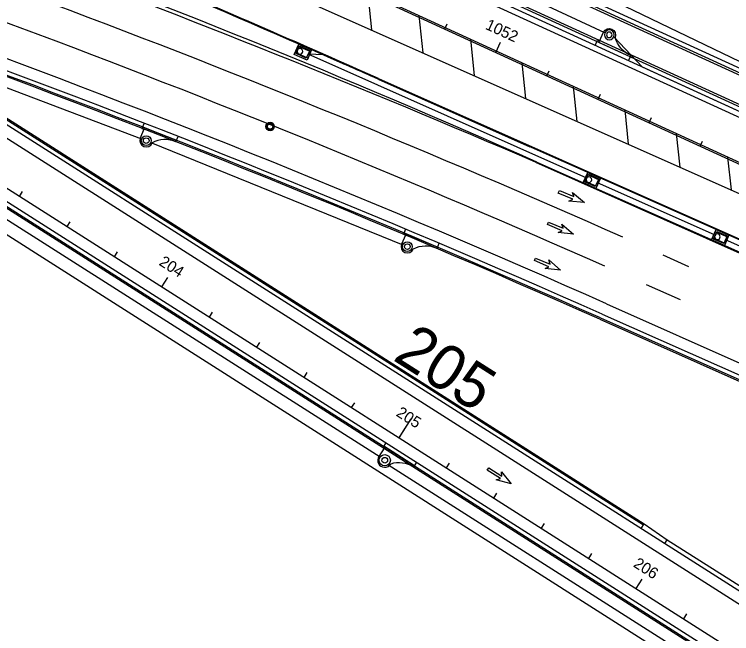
# Model space of a CAD drawing. Extents: x 468143 to 491361, y 1438528 to 1468730.
# Drawn here: x 487342.4 to 487597.7, y 1467031.9 to 1467252.2 of the extents above; entities that cross this region are included whole.
import ezdxf

# ---------------------------------------------------------------- set-up
doc = ezdxf.new("R2010")
doc.units = 0
doc.layers.add('Default', color=7, linetype='Continuous')
doc.layers.add('Xreference_dp', color=7, linetype='Continuous')

# ---------------------------------------------------------------- blocks, each defined once
blk = doc.blocks.new('POINT_DISPLAY')
at = {"layer": 'Default'}
blk.add_line((0, 0), (0, 0), dxfattribs=at)
blk = doc.blocks.new('InltCurb1_35')
at = {"layer": 'Default'}
for p, q in [((2.25, 2), (2.25, 5.5)), ((-10, 2), (-10, 0)), ((-10, 1.5), (3, 1.5)), ((3, 2), (2.25, 2)), ((3, 0), (3, 2))]:
    blk.add_line(p, q, dxfattribs=at)
for radius in [1.75, 1]:
    blk.add_circle((0, 5.5), radius, dxfattribs=at)
for centre, radius, start, end in [((0, 5.5), 2.25, 0, 180), ((-9.85, 12), 10, 269.1432, 319.4677)]:
    blk.add_arc(centre, radius, start, end, dxfattribs=at)
for p in [(0, 7.75), (-1.75, 5.5), (-1.75, 5.5), (-1.6, 6.2), (-1.22, 6.76), (-0.66, 7.12), (0, 7.25), (0, 7.25), (0, 5.5), (0, 5.5), (0.7, 7.1), (1.26, 6.72), (1.62, 6.16), (1.75, 5.5), (1.75, 5.5), (-1.62, 4.84), (-1.26, 4.28), (-0.7, 3.9), (0, 3.75), (0, 3.75), (0.66, 3.88), (1.22, 4.24), (1.6, 4.8), (0, 0), (0, 0)]:
    blk.add_blockref('POINT_DISPLAY', p, dxfattribs=at)
blk = doc.blocks.new('InltCurb7_40')
at = {"layer": 'Default'}
for p, q in [((2.5, 4), (-2.5, 4)), ((-2.5, 4), (-2.5, 0)), ((2.5, 3.25), (-2.5, 3.25)), ((2.5, 0), (2.5, 4)), ((-2.5, 0.75), (2.5, 0.75)), ((-2.5, 0), (2.5, 0))]:
    blk.add_line(p, q, dxfattribs=at)
blk.add_lwpolyline([(-2, 0.5), (2, 0.5), (2, 3.5), (-2, 3.5)], close=True, dxfattribs=at)
blk.add_circle((-1.04, 2.19), 1, dxfattribs=at)
for p in [(-2, 3.5), (0, 4), (0, 3.5), (0, 3.5), (2, 3.5), (-2, 2), (-2, 2), (-2, 0.5), (0, 2), (0, 2), (0, 0.5), (0, 0.5), (0, 0), (0, 0), (2, 2), (2, 2), (2, 0.5)]:
    blk.add_blockref('POINT_DISPLAY', p, dxfattribs=at)
blk = doc.blocks.new('MH2')
at = {"layer": 'Default'}
for p, q in [((-1.25, 0.03), (-1.05, 0.03)), ((-0.9, 0.87), (-0.76, 0.73)), ((-0.87, 0.9), (-0.73, 0.76)), ((-0.03, 1.25), (-0.03, 1.05)), ((0.03, 1.25), (0.03, 1.05)), ((0.87, 0.9), (0.73, 0.76)), ((0.9, 0.87), (0.76, 0.73)), ((1.05, 0.03), (1.25, 0.03)), ((-1.25, -0.03), (-1.05, -0.03)), ((-0.76, -0.73), (-0.9, -0.87)), ((-0.73, -0.76), (-0.87, -0.9)), ((-0.03, -1.05), (-0.03, -1.25)), ((0.03, -1.05), (0.03, -1.25)), ((0.73, -0.76), (0.87, -0.9)), ((0.76, -0.73), (0.9, -0.87)), ((1.05, -0.03), (1.25, -0.03))]:
    blk.add_line(p, q, dxfattribs=at)
for radius in [1.5, 1.25, 1.05, 1, 0.958]:
    blk.add_circle((0, 0), radius, dxfattribs=at)
for p in [(-1, 0), (-0.71, 0.71), (0, 1.5), (0, 1), (0, 0), (0, 0), (0, 0), (0.71, 0.71), (1, 0), (-0.71, -0.71), (0, -1), (0, -1.5), (0.71, -0.71)]:
    blk.add_blockref('POINT_DISPLAY', p, dxfattribs=at)
blk = doc.blocks.new('DAMerge_2')
at = {"layer": 'Default'}
blk.add_lwpolyline([(0.71, -4.09), (0, -3.39), (3.95, 0.56), (2.42, 0.68), (7.31, 3.21), (4.77, -1.68), (4.66, -0.15), (0.71, -4.09)], dxfattribs=at)
blk = doc.blocks.new('DAMerge_6')
at = {"layer": 'Default'}
blk.add_lwpolyline([(0.71, -4.09), (0, -3.39), (3.95, 0.56), (2.42, 0.68), (7.31, 3.21), (4.77, -1.68), (4.66, -0.15), (0.71, -4.09)], dxfattribs=at)

msp = doc.modelspace()

# ---------------------------------------------------------------- linework, layer by layer
at = {"layer": 'Xreference_dp'}
for p, q in [((487896.93, 1467095.38), (487480.75, 1467286.21)), ((487897.55, 1467096.74), (487481.23, 1467287.63)), ((487892.66, 1467086.06), (487461.92, 1467283.57)), ((487552.54, 1467245.59), (487468.38, 1467284.92)), ((487896.62, 1467094.69), (487480.46, 1467285.51)), ((487416.58, 1467283.18), (488348.99, 1466855.64)), ((487891.72, 1467084.01), (487460.98, 1467281.52)), ((487892.34, 1467085.38), (487461.6, 1467282.88)), ((487890.89, 1467082.19), (487460.14, 1467279.7)), ((487520.69, 1467273.94), (487700.82, 1467186.95)), ((487884.84, 1467069.01), (487440.18, 1467272.9)), ((487435.5, 1467261.72), (487882.12, 1467063.09)), ((487468.09, 1467260.11), (487469.52, 1467246.59)), ((487486.39, 1467251.72), (487487.79, 1467238.46)), ((487495.58, 1467246.95), (487496.42, 1467248.77)), ((487504.69, 1467243.32), (487506.07, 1467230.34)), ((487565.95, 1467233.39), (487555.72, 1467244.13)), ((487513.76, 1467238.62), (487515.43, 1467242.25)), ((487546.09, 1467193.91), (487446.93, 1467237.93)), ((487452.42, 1467237.7), (487446.93, 1467237.93)), ((487523, 1467234.93), (487524.34, 1467222.21)), ((487307.99, 1467233.04), (487708.93, 1466978.07)), ((487308.8, 1467234.3), (487566.29, 1467070.56)), ((487309.07, 1467234.72), (487566.55, 1467070.98)), ((487316.92, 1467234.65), (487387.74, 1467207.88)), ((487639.02, 1467199.88), (487565.95, 1467233.39)), ((487276.73, 1467230.4), (487829.84, 1466878.67)), ((487305.02, 1467230.19), (487766.73, 1466936.58)), ((487531.94, 1467230.28), (487532.78, 1467232.1)), ((487471.86, 1467229.11), (487875.87, 1467049.46)), ((487471.86, 1467229.11), (487525.89, 1467205.08)), ((487471.96, 1467229.34), (487875.98, 1467049.69)), ((487541.3, 1467226.54), (487542.62, 1467214.08)), ((487550.12, 1467221.94), (487550.96, 1467223.76)), ((487296.97, 1467217.53), (487758.68, 1466923.92)), ((487559.6, 1467218.15), (487560.89, 1467205.95)), ((487568.3, 1467213.61), (487569.14, 1467215.42)), ((487294.58, 1467211.94), (487628.01, 1466999.9)), ((487294.85, 1467212.36), (487628.28, 1467000.33)), ((487295.65, 1467213.63), (487790.32, 1466899.06)), ((487472.56, 1467094.61), (487289.13, 1467211.26)), ((487577.91, 1467209.75), (487579.17, 1467197.83)), ((487586.48, 1467205.27), (487587.32, 1467207.09)), ((487290.29, 1467205.19), (487623.72, 1466993.15)), ((487390.99, 1467206.6), (487480.66, 1467170.2)), ((487527.87, 1467199.55), (487874.1, 1467045.59)), ((487528.34, 1467199.61), (487874.21, 1467045.82)), ((487596.21, 1467201.36), (487597.44, 1467189.7)), ((487591.78, 1467173.59), (487549.75, 1467192.28)), ((487344.33, 1467187.41), (487345.4, 1467189.1)), ((487361.2, 1467176.68), (487362.28, 1467178.37)), ((487637.47, 1467153.28), (487595.44, 1467171.97)), ((487378.08, 1467165.95), (487379.15, 1467167.64)), ((487573.13, 1467166.56), (487582.27, 1467162.5)), ((487394.96, 1467155.22), (487397.1, 1467158.59)), ((487567.22, 1467156.06), (487579.33, 1467150.68)), ((487553.17, 1467149.17), (487859.2, 1467013.1)), ((487411.83, 1467144.49), (487412.91, 1467146.17)), ((487551.55, 1467145.52), (487857.53, 1467009.46)), ((487550.74, 1467143.69), (487856.7, 1467007.64)), ((487550.94, 1467144.15), (487856.91, 1467008.1)), ((487428.71, 1467133.75), (487429.78, 1467135.44)), ((487445.59, 1467123.02), (487446.66, 1467124.71)), ((487462.46, 1467112.29), (487463.54, 1467113.98)), ((487479.34, 1467101.56), (487483.63, 1467108.31)), ((487479.34, 1467101.56), (487481.49, 1467104.93)), ((487474.66, 1467099.79), (487473.59, 1467098.1)), ((487474.01, 1467097.84), (487472.13, 1467094.88)), ((487473.59, 1467098.1), (487474.01, 1467097.84)), ((487484.83, 1467091.55), (487473.86, 1467098.53)), ((487607.29, 1467008.04), (487475.36, 1467091.88)), ((487484.56, 1467091.13), (487485.63, 1467092.82)), ((487496.22, 1467090.83), (487497.29, 1467092.51)), ((487513.09, 1467080.09), (487514.17, 1467081.78)), ((487529.97, 1467069.36), (487531.04, 1467071.05)), ((487565.48, 1467069.3), (487566.55, 1467070.98)), ((487566.55, 1467070.98), (487574.75, 1467065.23)), ((487573.92, 1467063.93), (487574.75, 1467065.23)), ((487574.75, 1467065.23), (487709.71, 1466979.4)), ((487546.85, 1467058.63), (487547.92, 1467060.32)), ((487563.72, 1467047.9), (487565.87, 1467051.27)), ((487580.6, 1467037.16), (487581.67, 1467038.85))]:
    msp.add_line(p, q, dxfattribs=at)
for radius in [2, 1]:
    msp.add_circle((487474.24, 1467093.54), radius, dxfattribs=at)
for centre, radius, start, end in [((486023.86, 1463709.86), 3800, 66.68453, 72.73052), ((486023.86, 1463709.86), 3788, 66.09315, 72.73052), ((486023.86, 1463709.86), 3776, 66.11865, 72.73052), ((485288.17, 1462318.17), 5374.55, 66.0273, 67.70446), ((486236.65, 1464294.69), 3179.16, 66.0273, 70.00614), ((485288.17, 1462318.17), 5374.55, 66.41645, 66.83583), ((485288.17, 1462318.17), 5374.8, 66.0273, 66.72566), ((486023.86, 1463709.86), 3764, 66.0273, 69.97233), ((486023.86, 1463709.86), 3760, 66.0273, 69.97233), ((486023.86, 1463709.86), 3758, 66.0273, 69.97233), ((486023.86, 1463709.86), 3758.5, 66.0273, 69.97233), ((485288.17, 1462318.17), 5374.55, 66.0273, 66.25386), ((487474.24, 1467093.54), 2.5, 147.547, 327.547), ((487479.28, 1467082.64), 10, 58.1186, 107.0091)]:
    msp.add_arc(centre, radius, start, end, dxfattribs=at)

# ---------------------------------------------------------------- block references
for name, p, yscale, rotation in [('InltCurb1_35', (487551.84, 1467239.86), -1.0000000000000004, 155.36711924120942), ('InltCurb7_40', (487445.9, 1467240.57), -1, -23.695411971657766), ('InltCurb7_40', (487548.73, 1467194.92), -0.9999999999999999, -23.972703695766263), ('InltCurb7_40', (487594.42, 1467174.61), -0.9999999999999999, -23.972703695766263)]:
    msp.add_blockref(name, p, dxfattribs=dict(at, yscale=yscale, rotation=rotation))
for name, p, rotation in [('InltCurb1_35', (487391.37, 1467212.36), 158.61417907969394), ('MH2', (487433.44, 1467212.26), 65.36711924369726), ('DAMerge_2', (487539.5, 1467190.77), -67.66514950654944), ('DAMerge_6', (487539.5, 1467190.77), -67.66514950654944), ('DAMerge_2', (487535.67, 1467179.55), -67.66514950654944), ('DAMerge_6', (487535.67, 1467179.55), -67.66514950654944), ('InltCurb1_35', (487484.41, 1467174.59), 157.16514270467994), ('DAMerge_2', (487531.04, 1467166.75), -67.66514950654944), ('DAMerge_6', (487531.04, 1467166.75), -67.66514950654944), ('POINT_DISPLAY', (487477.19, 1467098.18), 147.54695753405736), ('POINT_DISPLAY', (487477.19, 1467098.18), 147.54695753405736), ('POINT_DISPLAY', (487472.56, 1467094.61), 147.54695753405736), ('POINT_DISPLAY', (487472.56, 1467094.61), 147.54695753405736), ('POINT_DISPLAY', (487473.13, 1467095.2), 147.54695753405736), ('POINT_DISPLAY', (487473.84, 1467095.5), 147.54695753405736), ('POINT_DISPLAY', (487474.6, 1467095.51), 147.54695753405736), ('POINT_DISPLAY', (487475.32, 1467095.23), 147.54695753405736), ('POINT_DISPLAY', (487475.32, 1467095.23), 147.54695753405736), ('POINT_DISPLAY', (487475.91, 1467094.65), 147.54695753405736), ('POINT_DISPLAY', (487472.28, 1467093.9), 147.54695753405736), ('POINT_DISPLAY', (487472.28, 1467093.13), 147.54695753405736), ('POINT_DISPLAY', (487472.58, 1467092.43), 147.54695753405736), ('POINT_DISPLAY', (487473.17, 1467091.85), 147.54695753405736), ('POINT_DISPLAY', (487473.17, 1467091.85), 147.54695753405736), ('POINT_DISPLAY', (487474.24, 1467093.54), 147.54695753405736), ('POINT_DISPLAY', (487474.24, 1467093.54), 147.54695753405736), ('POINT_DISPLAY', (487475.36, 1467091.88), 147.54695753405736), ('POINT_DISPLAY', (487475.93, 1467092.47), 147.54695753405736), ('POINT_DISPLAY', (487475.93, 1467092.47), 147.54695753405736), ('POINT_DISPLAY', (487476.2, 1467093.95), 147.54695753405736), ('POINT_DISPLAY', (487476.21, 1467093.18), 147.54695753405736), ('DAMerge_2', (487514.57, 1467091.6), -78.07809229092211), ('DAMerge_6', (487514.57, 1467091.6), -78.07809229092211), ('POINT_DISPLAY', (487472.9, 1467091.43), 147.54695753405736), ('POINT_DISPLAY', (487473.88, 1467091.57), 147.54695753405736), ('POINT_DISPLAY', (487474.65, 1467091.58), 147.54695753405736)]:
    msp.add_blockref(name, p, dxfattribs=dict(at, rotation=rotation))

# ---------------------------------------------------------------- texts
for s, height, rotation, p in [('1052', 4, 335.3671, (487509.73, 1467247.06)), ('204', 4, 327.547, (487393.63, 1467163.17)), ('205', 16, 327.547, (487476.7, 1467129.42)), ('205', 4, 327.547, (487478.01, 1467109.51)), ('206', 4, 327.547, (487562.4, 1467055.85))]:
    msp.add_text(s, height=height, rotation=rotation, dxfattribs=at).set_placement(p)

doc.saveas('drawing.dxf')
